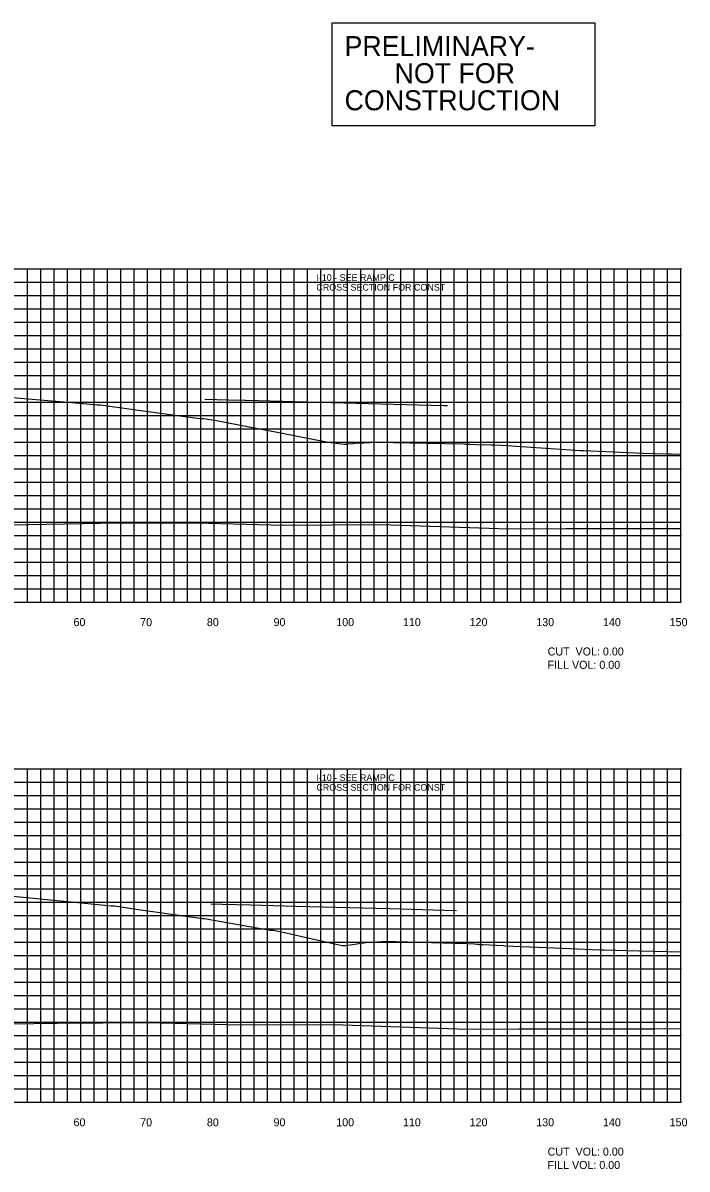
# Model space of a CAD drawing. Extents: x 1800880 to 1814006, y 250083 to 250560.
# Drawn here: x 1810162.3 to 1810261.9, y 250089.4 to 250261.3 of the extents above; entities that cross this region are included whole.
import ezdxf

# ---------------------------------------------------------------- set-up
doc = ezdxf.new("R2010")
doc.units = 0
for name, color, linetype in [('CL-CNST', 7, 'Continuous'), ('DESIGN - DRAINAGE - Bridges', 7, 'Continuous'), ('DRAINAGETXT', 7, 'Continuous'), ('EPTEXT', 7, 'Continuous'), ('Level 32', 7, 'Continuous'), ('Level 46', 7, 'Continuous'), ('Level 62', 7, 'Continuous')]:
    doc.layers.add(name, color=color, linetype=linetype)

msp = doc.modelspace()

# ---------------------------------------------------------------- linework, layer by layer
at = {"layer": 'CL-CNST'}
for points in [[(1810160.12, 250205.19), (1810169.66, 250204.38), (1810173.44, 250204), (1810173.67, 250204), (1810173.94, 250204), (1810178.92, 250203.32), (1810188.85, 250201.96), (1810188.94, 250201.96), (1810189.39, 250201.95), (1810191.05, 250201.7), (1810191.1, 250201.7), (1810196.49, 250200.65), (1810197.25, 250200.5), (1810198.62, 250200.25), (1810208.11, 250198.44), (1810210.47, 250198.14), (1810210.82, 250198.14), (1810210.85, 250198.16), (1810211.83, 250198.24), (1810212.38, 250198.33), (1810212.56, 250198.33), (1810212.58, 250198.33), (1810212.6, 250198.33), (1810212.62, 250198.33), (1810212.64, 250198.33), (1810212.67, 250198.33), (1810212.69, 250198.33), (1810212.73, 250198.33), (1810212.76, 250198.33), (1810212.81, 250198.33), (1810212.86, 250198.33), (1810212.92, 250198.33), (1810212.99, 250198.33), (1810213.08, 250198.33), (1810213.19, 250198.33), (1810213.33, 250198.33), (1810213.4, 250198.33), (1810213.46, 250198.33), (1810213.81, 250198.35), (1810214.32, 250198.37), (1810215.14, 250198.4), (1810215.37, 250198.41), (1810222.83, 250198.28), (1810228.5, 250198.17), (1810228.64, 250198.16), (1810228.83, 250198.14), (1810228.99, 250198.13), (1810229.12, 250198.12), (1810229.23, 250198.11), (1810229.32, 250198.1), (1810231.26, 250198), (1810231.46, 250198.06), (1810232.51, 250198), (1810232.62, 250198), (1810233.08, 250198), (1810234.87, 250197.9), (1810245.88, 250197.19), (1810246.16, 250197.19), (1810246.39, 250197.19), (1810255.27, 250196.77), (1810259.01, 250196.66), (1810259.36, 250196.66), (1810259.52, 250196.66), (1810261, 250196.62)], [(1810160.79, 250130.35), (1810170.53, 250129.4), (1810175.56, 250128.87), (1810175.72, 250128.87), (1810176.07, 250128.87), (1810179.63, 250128.36), (1810189.22, 250126.99), (1810189.53, 250126.99), (1810198.54, 250125.39), (1810199.2, 250125.28), (1810199.34, 250125.26), (1810199.84, 250125.26), (1810199.85, 250125.26), (1810201.79, 250124.82), (1810204.59, 250124.18), (1810209.28, 250123.14), (1810209.31, 250123.14), (1810210.17, 250122.94), (1810210.63, 250122.94), (1810210.66, 250122.94), (1810211.74, 250123.11), (1810213.04, 250123.28), (1810214.1, 250123.44), (1810215.38, 250123.49), (1810216.08, 250123.52), (1810217.15, 250123.56), (1810218.2, 250123.52), (1810228.95, 250123.26), (1810228.97, 250123.26), (1810230.04, 250123.17), (1810230.38, 250123.14), (1810230.54, 250123.13), (1810230.64, 250123.12), (1810230.7, 250123.12), (1810230.74, 250123.11), (1810230.78, 250123.11), (1810230.8, 250123.11), (1810230.82, 250123.11), (1810230.84, 250123.1), (1810230.85, 250123.1), (1810230.86, 250123.1), (1810230.87, 250123.1), (1810231.08, 250123.09), (1810231.1, 250123.1), (1810231.21, 250123.09), (1810231.22, 250123.09), (1810231.27, 250123.09), (1810234.4, 250122.92), (1810234.62, 250122.91), (1810242.02, 250122.58), (1810248.85, 250122.29), (1810249.12, 250122.29), (1810249.36, 250122.3), (1810254.77, 250122.14), (1810261, 250121.97)]]:
    msp.add_lwpolyline(points, dxfattribs=at)
at = {"layer": 'DESIGN - DRAINAGE - Bridges'}
for p, q in [((1810261, 250174.43), (1810261, 250224.43)), ((1810261.06, 250224.43), (1810261, 250224.43)), ((1810261.06, 250214.43), (1810261, 250214.43)), ((1810261.06, 250204.43), (1810261, 250204.43)), ((1810261.06, 250194.43), (1810261, 250194.43)), ((1810261.06, 250184.43), (1810261, 250184.43)), ((1809961, 250174.43), (1810261, 250174.43)), ((1810171, 250174.37), (1810171, 250174.43)), ((1810181, 250174.37), (1810181, 250174.43)), ((1810191, 250174.37), (1810191, 250174.43)), ((1810201, 250174.37), (1810201, 250174.43)), ((1810211, 250174.37), (1810211, 250174.43)), ((1810221, 250174.37), (1810221, 250174.43)), ((1810231, 250174.37), (1810231, 250174.43)), ((1810241, 250174.37), (1810241, 250174.43)), ((1810251, 250174.37), (1810251, 250174.43)), ((1810261, 250174.37), (1810261, 250174.43)), ((1810261.06, 250174.43), (1810261, 250174.43)), ((1810261, 250099.43), (1810261, 250149.43)), ((1810261.06, 250149.43), (1810261, 250149.43)), ((1810261.06, 250139.43), (1810261, 250139.43)), ((1810261.06, 250129.43), (1810261, 250129.43)), ((1810261.06, 250119.43), (1810261, 250119.43)), ((1810261.06, 250109.43), (1810261, 250109.43)), ((1809961, 250099.43), (1810261, 250099.43)), ((1810171, 250099.37), (1810171, 250099.43)), ((1810181, 250099.37), (1810181, 250099.43)), ((1810191, 250099.37), (1810191, 250099.43)), ((1810201, 250099.37), (1810201, 250099.43)), ((1810211, 250099.37), (1810211, 250099.43)), ((1810221, 250099.37), (1810221, 250099.43)), ((1810231, 250099.37), (1810231, 250099.43)), ((1810241, 250099.37), (1810241, 250099.43)), ((1810251, 250099.37), (1810251, 250099.43)), ((1810261, 250099.37), (1810261, 250099.43)), ((1810261.06, 250099.43), (1810261, 250099.43))]:
    msp.add_line(p, q, dxfattribs=at)
at = {"layer": 'Level 32'}
msp.add_lwpolyline([(1810208.68, 250261.29), (1810248.08, 250261.29), (1810248.08, 250245.85), (1810208.68, 250245.85)], close=True, dxfattribs=at)
at = {"layer": 'Level 46'}
for p, q in [((1809961, 250224.43), (1810261, 250224.43)), ((1810163, 250174.43), (1810163, 250224.43)), ((1810165, 250174.43), (1810165, 250224.43)), ((1810167, 250174.43), (1810167, 250224.43)), ((1810169, 250174.43), (1810169, 250224.43)), ((1810171, 250174.43), (1810171, 250224.43)), ((1810173, 250174.43), (1810173, 250224.43)), ((1810175, 250174.43), (1810175, 250224.43)), ((1810177, 250174.43), (1810177, 250224.43)), ((1810179, 250174.43), (1810179, 250224.43)), ((1810181, 250174.43), (1810181, 250224.43)), ((1810183, 250174.43), (1810183, 250224.43)), ((1810185, 250174.43), (1810185, 250224.43)), ((1810187, 250174.43), (1810187, 250224.43)), ((1810189, 250174.43), (1810189, 250224.43)), ((1810191, 250174.43), (1810191, 250224.43)), ((1810193, 250174.43), (1810193, 250224.43)), ((1810195, 250174.43), (1810195, 250224.43)), ((1810197, 250174.43), (1810197, 250224.43)), ((1810199, 250174.43), (1810199, 250224.43)), ((1810201, 250174.43), (1810201, 250224.43)), ((1810203, 250174.43), (1810203, 250224.43)), ((1810205, 250174.43), (1810205, 250224.43)), ((1810207, 250174.43), (1810207, 250224.43)), ((1810209, 250174.43), (1810209, 250224.43)), ((1810211, 250174.43), (1810211, 250224.43)), ((1810213, 250174.43), (1810213, 250224.43)), ((1810215, 250174.43), (1810215, 250224.43)), ((1810217, 250174.43), (1810217, 250224.43)), ((1810219, 250174.43), (1810219, 250224.43)), ((1810221, 250174.43), (1810221, 250224.43)), ((1810223, 250174.43), (1810223, 250224.43)), ((1810225, 250174.43), (1810225, 250224.43)), ((1810227, 250174.43), (1810227, 250224.43)), ((1810229, 250174.43), (1810229, 250224.43)), ((1810231, 250174.43), (1810231, 250224.43)), ((1810233, 250174.43), (1810233, 250224.43)), ((1810235, 250174.43), (1810235, 250224.43)), ((1810237, 250174.43), (1810237, 250224.43)), ((1810239, 250174.43), (1810239, 250224.43)), ((1810241, 250174.43), (1810241, 250224.43)), ((1810243, 250174.43), (1810243, 250224.43)), ((1810245, 250174.43), (1810245, 250224.43)), ((1810247, 250174.43), (1810247, 250224.43)), ((1810249, 250174.43), (1810249, 250224.43)), ((1810251, 250174.43), (1810251, 250224.43)), ((1810253, 250174.43), (1810253, 250224.43)), ((1810255, 250174.43), (1810255, 250224.43)), ((1810257, 250174.43), (1810257, 250224.43)), ((1810259, 250174.43), (1810259, 250224.43)), ((1810261, 250174.43), (1810261, 250224.43)), ((1809961, 250222.43), (1810261, 250222.43)), ((1809961, 250220.43), (1810261, 250220.43)), ((1809961, 250218.43), (1810261, 250218.43)), ((1809961, 250216.43), (1810261, 250216.43)), ((1809961, 250214.43), (1810261, 250214.43)), ((1809961, 250212.43), (1810261, 250212.43)), ((1809961, 250210.43), (1810261, 250210.43)), ((1809961, 250208.43), (1810261, 250208.43)), ((1809961, 250206.43), (1810261, 250206.43)), ((1809961, 250204.43), (1810261, 250204.43)), ((1809961, 250202.43), (1810261, 250202.43)), ((1809961, 250200.43), (1810261, 250200.43)), ((1809961, 250198.43), (1810261, 250198.43)), ((1809961, 250196.43), (1810261, 250196.43)), ((1809961, 250194.43), (1810261, 250194.43)), ((1809961, 250192.43), (1810261, 250192.43)), ((1809961, 250190.43), (1810261, 250190.43)), ((1809961, 250188.43), (1810261, 250188.43)), ((1809961, 250186.43), (1810261, 250186.43)), ((1809961, 250184.43), (1810261, 250184.43)), ((1809961, 250182.43), (1810261, 250182.43)), ((1809961, 250180.43), (1810261, 250180.43)), ((1809961, 250178.43), (1810261, 250178.43)), ((1809961, 250176.43), (1810261, 250176.43)), ((1809961, 250174.43), (1810261, 250174.43)), ((1809961, 250149.43), (1810261, 250149.43)), ((1810163, 250099.43), (1810163, 250149.43)), ((1810165, 250099.43), (1810165, 250149.43)), ((1810167, 250099.43), (1810167, 250149.43)), ((1810169, 250099.43), (1810169, 250149.43)), ((1810171, 250099.43), (1810171, 250149.43)), ((1810173, 250099.43), (1810173, 250149.43)), ((1810175, 250099.43), (1810175, 250149.43)), ((1810177, 250099.43), (1810177, 250149.43)), ((1810179, 250099.43), (1810179, 250149.43)), ((1810181, 250099.43), (1810181, 250149.43)), ((1810183, 250099.43), (1810183, 250149.43)), ((1810185, 250099.43), (1810185, 250149.43)), ((1810187, 250099.43), (1810187, 250149.43)), ((1810189, 250099.43), (1810189, 250149.43)), ((1810191, 250099.43), (1810191, 250149.43)), ((1810193, 250099.43), (1810193, 250149.43)), ((1810195, 250099.43), (1810195, 250149.43)), ((1810197, 250099.43), (1810197, 250149.43)), ((1810199, 250099.43), (1810199, 250149.43)), ((1810201, 250099.43), (1810201, 250149.43)), ((1810203, 250099.43), (1810203, 250149.43)), ((1810205, 250099.43), (1810205, 250149.43)), ((1810207, 250099.43), (1810207, 250149.43)), ((1810209, 250099.43), (1810209, 250149.43)), ((1810211, 250099.43), (1810211, 250149.43)), ((1810213, 250099.43), (1810213, 250149.43)), ((1810215, 250099.43), (1810215, 250149.43)), ((1810217, 250099.43), (1810217, 250149.43)), ((1810219, 250099.43), (1810219, 250149.43)), ((1810221, 250099.43), (1810221, 250149.43)), ((1810223, 250099.43), (1810223, 250149.43)), ((1810225, 250099.43), (1810225, 250149.43)), ((1810227, 250099.43), (1810227, 250149.43)), ((1810229, 250099.43), (1810229, 250149.43)), ((1810231, 250099.43), (1810231, 250149.43)), ((1810233, 250099.43), (1810233, 250149.43)), ((1810235, 250099.43), (1810235, 250149.43)), ((1810237, 250099.43), (1810237, 250149.43)), ((1810239, 250099.43), (1810239, 250149.43)), ((1810241, 250099.43), (1810241, 250149.43)), ((1810243, 250099.43), (1810243, 250149.43)), ((1810245, 250099.43), (1810245, 250149.43)), ((1810247, 250099.43), (1810247, 250149.43)), ((1810249, 250099.43), (1810249, 250149.43)), ((1810251, 250099.43), (1810251, 250149.43)), ((1810253, 250099.43), (1810253, 250149.43)), ((1810255, 250099.43), (1810255, 250149.43)), ((1810257, 250099.43), (1810257, 250149.43)), ((1810259, 250099.43), (1810259, 250149.43)), ((1810261, 250099.43), (1810261, 250149.43)), ((1809961, 250147.43), (1810261, 250147.43)), ((1809961, 250145.43), (1810261, 250145.43)), ((1809961, 250143.43), (1810261, 250143.43)), ((1809961, 250141.43), (1810261, 250141.43)), ((1809961, 250139.43), (1810261, 250139.43)), ((1809961, 250137.43), (1810261, 250137.43)), ((1809961, 250135.43), (1810261, 250135.43)), ((1809961, 250133.43), (1810261, 250133.43)), ((1809961, 250131.43), (1810261, 250131.43)), ((1809961, 250129.43), (1810261, 250129.43)), ((1809961, 250127.43), (1810261, 250127.43)), ((1809961, 250125.43), (1810261, 250125.43)), ((1809961, 250123.43), (1810261, 250123.43)), ((1809961, 250121.43), (1810261, 250121.43)), ((1809961, 250119.43), (1810261, 250119.43)), ((1809961, 250117.43), (1810261, 250117.43)), ((1809961, 250115.43), (1810261, 250115.43)), ((1809961, 250113.43), (1810261, 250113.43)), ((1809961, 250111.43), (1810261, 250111.43)), ((1809961, 250109.43), (1810261, 250109.43)), ((1809961, 250107.43), (1810261, 250107.43)), ((1809961, 250105.43), (1810261, 250105.43)), ((1809961, 250103.43), (1810261, 250103.43)), ((1809961, 250101.43), (1810261, 250101.43)), ((1809961, 250099.43), (1810261, 250099.43))]:
    msp.add_line(p, q, dxfattribs=at)
at = {"layer": 'Level 62'}
for points in [[(1810189.58, 250204.87), (1810193.21, 250204.78), (1810195.59, 250204.71), (1810195.69, 250204.71), (1810215.97, 250204.18), (1810225.42, 250203.93), (1810226.01, 250203.91)], [(1809961, 250186.35), (1809966.2, 250186.32), (1809968.7, 250186.32), (1809993.95, 250186.14), (1809999.26, 250186.15), (1810021.71, 250185.99), (1810029.37, 250186.02), (1810049.46, 250185.95), (1810059.13, 250186), (1810077.22, 250186.02), (1810088.62, 250186.08), (1810104.98, 250185.8), (1810117.89, 250185.87), (1810132.73, 250186.03), (1810146.41, 250185.94), (1810160.49, 250186.03), (1810173.94, 250186.26), (1810188.24, 250186.34), (1810201.43, 250185.98), (1810216, 250186.08), (1810235.17, 250185.41), (1810243.75, 250185.47), (1810261, 250185.47)], [(1810190.5, 250129.18), (1810192.25, 250129.13), (1810196.51, 250129.02), (1810203.28, 250128.84), (1810217.31, 250128.47), (1810223.86, 250128.3), (1810227.36, 250128.21)], [(1809961, 250111.41), (1809986.87, 250111.22), (1809991.33, 250111.23), (1810014.62, 250111.07), (1810021.51, 250111.09), (1810042.38, 250111.02), (1810051.33, 250111.07), (1810070.13, 250111.09), (1810080.87, 250111.15), (1810097.89, 250110.85), (1810110.18, 250110.92), (1810125.65, 250111.09), (1810139.9, 250110.99), (1810153.4, 250111.08), (1810167.45, 250111.31), (1810181.16, 250111.4), (1810194.94, 250111.02), (1810208.91, 250111.11), (1810228.98, 250110.41), (1810236.67, 250110.47), (1810257.05, 250110.47), (1810261, 250110.49)]]:
    msp.add_lwpolyline(points, dxfattribs=at)

# ---------------------------------------------------------------- texts
for s, p in [('60', (1810169.9, 250170.83)), ('70', (1810179.9, 250170.83)), ('80', (1810189.9, 250170.83)), ('90', (1810199.9, 250170.83)), ('100', (1810209.3, 250170.83)), ('110', (1810219.3, 250170.83)), ('120', (1810229.3, 250170.83)), ('130', (1810239.3, 250170.83)), ('140', (1810249.3, 250170.83)), ('150', (1810259.3, 250170.83)), ('60', (1810169.9, 250095.83)), ('70', (1810179.9, 250095.83)), ('80', (1810189.9, 250095.83)), ('90', (1810199.9, 250095.83)), ('100', (1810209.3, 250095.83)), ('110', (1810219.3, 250095.83)), ('120', (1810229.3, 250095.83)), ('130', (1810239.3, 250095.83)), ('140', (1810249.3, 250095.83)), ('150', (1810259.3, 250095.83))]:
    msp.add_text(s, height=1.2).set_placement(p)
at = {"layer": 'DRAINAGETXT'}
for s, p in [('CUT  VOL: 0.00', (1810241, 250166.43)), ('FILL VOL: 0.00', (1810241, 250164.43)), ('CUT  VOL: 0.00', (1810241, 250091.43)), ('FILL VOL: 0.00', (1810241, 250089.43))]:
    msp.add_text(s, height=1.2, dxfattribs=at).set_placement(p)
at = {"layer": 'EPTEXT'}
for s, p in [('CROSS SECTION FOR CONST ', (1810206.32, 250221.15)), ('I-10 - SEE RAMP C', (1810206.32, 250222.6)), ('I-10 - SEE RAMP C', (1810206.32, 250147.6)), ('CROSS SECTION FOR CONST ', (1810206.32, 250146.15))]:
    msp.add_text(s, height=1, dxfattribs=at).set_placement(p)
at = {"layer": 'Level 32'}
for s, p in [('PRELIMINARY-', (1810210.54, 250256.31)), ('NOT FOR', (1810218.05, 250252.25)), ('CONSTRUCTION', (1810210.55, 250248.19))]:
    msp.add_text(s, height=3, dxfattribs=at).set_placement(p)

doc.saveas('drawing.dxf')
